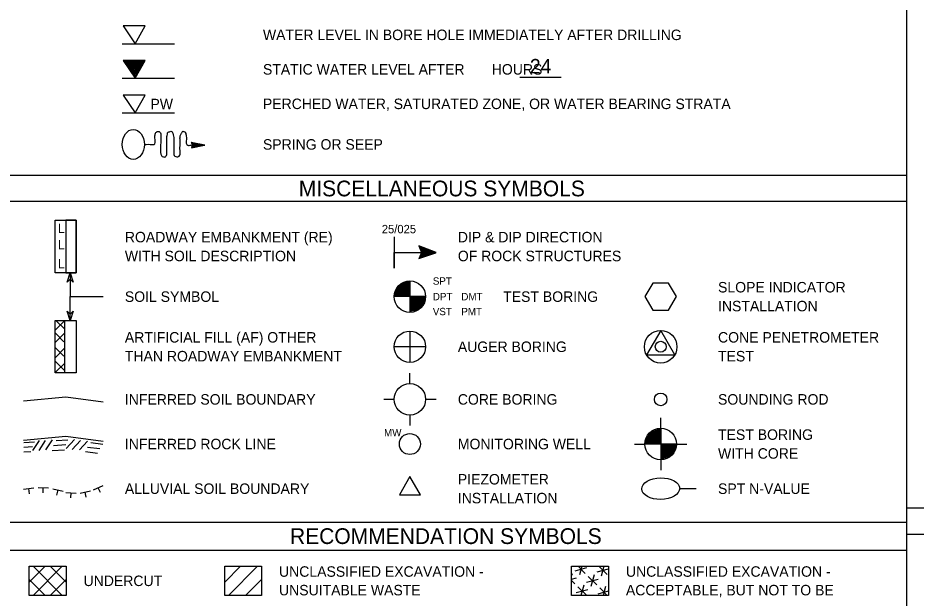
# Model space of a CAD drawing. Extents: x 278618 to 280654, y 171155 to 171855.
# Drawn here: x 280512.35 to 280549.54, y 171574.37 to 171598.38 of the extents above; entities that cross this region are included whole.
import ezdxf

# ---------------------------------------------------------------- set-up
doc = ezdxf.new("R2010")
doc.units = 0
doc.layers.add('Geotech Sheets and Borders Cell', color=7, linetype='Continuous')

msp = doc.modelspace()

# ---------------------------------------------------------------- linework, layer by layer
at = {"layer": 'Geotech Sheets and Borders Cell'}
for p, q in [((280549.148, 171621.702), (280549.148, 171541.488)), ((280516.664, 171597.314), (280518.833, 171597.314)), ((280516.664, 171595.886), (280518.833, 171595.886)), ((280533.134, 171595.924), (280534.838, 171595.924)), ((280516.664, 171594.459), (280518.833, 171594.459)), ((280520.093, 171593.12), (280519.52, 171593.228)), ((280519.52, 171593.228), (280519.581, 171593.124)), ((280519.581, 171593.124), (280519.529, 171593.011)), ((280519.529, 171593.011), (280520.079, 171593.115)), ((280519.568, 171593.102), (280519.819, 171593.15)), ((280519.568, 171593.102), (280519.819, 171593.15)), ((280519.568, 171593.098), (280519.819, 171593.146)), ((280519.568, 171593.094), (280519.819, 171593.141)), ((280519.568, 171593.089), (280519.819, 171593.137)), ((280519.568, 171593.085), (280519.819, 171593.133)), ((280519.568, 171593.085), (280519.819, 171593.133)), ((280519.572, 171593.081), (280519.824, 171593.128)), ((280519.572, 171593.076), (280519.824, 171593.124)), ((280519.572, 171593.072), (280519.824, 171593.12)), ((280519.572, 171593.068), (280519.824, 171593.115)), ((280519.572, 171593.063), (280519.824, 171593.111)), ((280519.572, 171593.059), (280519.824, 171593.107)), ((280519.572, 171593.059), (280519.824, 171593.107)), ((280519.576, 171593.141), (280519.832, 171593.098)), ((280519.576, 171593.141), (280519.832, 171593.098)), ((280519.576, 171593.137), (280519.832, 171593.094)), ((280519.576, 171593.055), (280519.828, 171593.102)), ((280519.576, 171593.05), (280519.828, 171593.098)), ((280519.576, 171593.046), (280519.828, 171593.094)), ((280519.576, 171593.042), (280519.828, 171593.089)), ((280519.576, 171593.042), (280519.828, 171593.089)), ((280519.576, 171593.037), (280519.828, 171593.085)), ((280519.581, 171593.172), (280519.837, 171593.128)), ((280519.581, 171593.167), (280519.837, 171593.124)), ((280519.581, 171593.163), (280519.837, 171593.12)), ((280519.581, 171593.159), (280519.837, 171593.115)), ((280519.581, 171593.154), (280519.837, 171593.111)), ((280519.581, 171593.15), (280519.837, 171593.107)), ((280519.581, 171593.033), (280519.832, 171593.081)), ((280519.585, 171593.193), (280519.841, 171593.15)), ((280519.585, 171593.185), (280519.841, 171593.141)), ((280519.585, 171593.18), (280519.841, 171593.137)), ((280519.585, 171593.176), (280519.841, 171593.133)), ((280519.589, 171593.198), (280519.845, 171593.154)), ((280519.594, 171593.206), (280520.062, 171593.12)), ((280549.148, 171591.865), (280474.148, 171591.865)), ((280549.148, 171590.781), (280474.148, 171590.781)), ((280514.329, 171590.004), (280514.329, 171587.835)), ((280528.578, 171587.496), (280528.578, 171586.195)), ((280529.229, 171586.846), (280527.928, 171586.846)), ((280513.9, 171585.47), (280514.273, 171585.843)), ((280514.273, 171585.509), (280513.921, 171585.861)), ((280514.281, 171585.83), (280514.281, 171583.679)), ((280513.891, 171584.941), (280514.281, 171585.332)), ((280514.255, 171584.98), (280513.9, 171585.336)), ((280528.578, 171585.423), (280528.578, 171584.121)), ((280514.255, 171584.386), (280513.908, 171584.733)), ((280529.229, 171584.772), (280527.928, 171584.772)), ((280513.9, 171584.329), (280514.281, 171584.711)), ((280513.904, 171583.713), (280514.286, 171584.095)), ((280514.277, 171583.792), (280513.908, 171584.16)), ((280528.578, 171583.248), (280528.578, 171583.682)), ((280527.494, 171582.597), (280527.928, 171582.597)), ((280529.229, 171582.597), (280529.663, 171582.597)), ((280528.578, 171581.947), (280528.578, 171581.513)), ((280538.965, 171581.396), (280538.965, 171581.83)), ((280538.965, 171581.396), (280538.965, 171580.095)), ((280512.599, 171580.811), (280513.037, 171580.842)), ((280512.599, 171580.62), (280512.946, 171580.642)), ((280512.963, 171580.473), (280513.237, 171580.889)), ((280513.224, 171580.477), (280513.493, 171580.894)), ((280513.51, 171580.508), (280513.779, 171580.924)), ((280513.822, 171580.686), (280514.33, 171580.72)), ((280513.926, 171580.889), (280514.421, 171580.92)), ((280514.351, 171580.564), (280514.69, 171580.928)), ((280514.599, 171580.521), (280514.941, 171580.889)), ((280514.898, 171580.499), (280515.228, 171580.863)), ((280515.371, 171580.803), (280515.865, 171580.746)), ((280537.88, 171580.746), (280538.314, 171580.746)), ((280539.615, 171580.746), (280538.314, 171580.746)), ((280539.615, 171580.746), (280540.049, 171580.746)), ((280512.599, 171580.417), (280512.885, 171580.434)), ((280513.77, 171580.482), (280514.273, 171580.512)), ((280515.145, 171580.434), (280515.644, 171580.369)), ((280515.228, 171580.62), (280515.74, 171580.564)), ((280538.965, 171580.095), (280538.965, 171579.661)), ((280512.581, 171578.876), (280513.011, 171578.937)), ((280512.828, 171578.69), (280512.798, 171578.907)), ((280513.18, 171578.941), (280513.614, 171578.928)), ((280513.392, 171578.72), (280513.397, 171578.933)), ((280513.8, 171578.898), (280514.221, 171578.789)), ((280513.956, 171578.633), (280514.013, 171578.846)), ((280514.924, 171578.711), (280515.349, 171578.802)), ((280515.475, 171578.85), (280515.874, 171579.024)), ((280515.761, 171578.737), (280515.674, 171578.937)), ((280539.752, 171578.909), (280540.438, 171578.909)), ((280514.329, 171578.737), (280514.763, 171578.716)), ((280514.538, 171578.512), (280514.546, 171578.724)), ((280515.18, 171578.547), (280515.136, 171578.759)), ((280549.148, 171578.101), (280588.802, 171578.101)), ((280474.148, 171577.514), (280549.148, 171577.514)), ((280549.148, 171577.016), (280588.802, 171577.016)), ((280474.148, 171576.353), (280549.148, 171576.353)), ((280512.854, 171575.686), (280512.817, 171575.649)), ((280513.474, 171575.686), (280512.817, 171575.029)), ((280514.181, 171575.686), (280512.977, 171574.482)), ((280512.977, 171575.686), (280514.181, 171574.482)), ((280513.684, 171575.686), (280514.341, 171575.029)), ((280520.91, 171575.029), (280521.567, 171575.686)), ((280521.071, 171574.482), (280522.274, 171575.686)), ((280535.423, 171575.504), (280535.906, 171575.633)), ((280535.547, 171575.686), (280535.841, 171575.392)), ((280535.696, 171575.686), (280535.6, 171575.327)), ((280536.33, 171575.456), (280536.801, 171575.583)), ((280536.407, 171575.686), (280536.748, 171575.344)), ((280536.616, 171575.686), (280536.507, 171575.28)), ((280512.817, 171575.139), (280513.474, 171574.482)), ((280514.341, 171575.139), (280513.684, 171574.482)), ((280521.778, 171574.482), (280522.434, 171575.139)), ((280535.299, 171575.38), (280535.277, 171575.298)), ((280535.277, 171575.15), (280535.476, 171575.203)), ((280535.277, 171575.096), (280535.411, 171574.962)), ((280535.9, 171575.026), (280536.383, 171575.156)), ((280535.965, 171575.268), (280536.318, 171574.914)), ((280536.206, 171575.333), (280536.077, 171574.85)), ((280535.47, 171574.596), (280535.953, 171574.726)), ((280535.535, 171574.838), (280535.888, 171574.484)), ((280535.776, 171574.903), (280535.664, 171574.482)), ((280536.442, 171574.791), (280536.75, 171574.482)), ((280536.684, 171574.855), (280536.584, 171574.482)), ((280536.377, 171574.549), (280536.801, 171574.663))]:
    msp.add_line(p, q, dxfattribs=at)
for points in [[(280517.198, 171597.314), (280517.622, 171598.048), (280516.711, 171598.048), (280517.198, 171597.314)], [(280517.198, 171595.886), (280517.622, 171596.619), (280516.711, 171596.619), (280517.198, 171595.886)], [(280516.755, 171596.593), (280517.592, 171596.593), (280517.197, 171595.925), (280516.755, 171596.593)], [(280516.802, 171596.567), (280517.553, 171596.567), (280517.197, 171595.964), (280516.811, 171596.545), (280517.527, 171596.545), (280517.197, 171596.003), (280516.846, 171596.524), (280517.488, 171596.524), (280517.197, 171596.051), (280516.893, 171596.498), (280517.444, 171596.498), (280517.193, 171596.098), (280516.933, 171596.472), (280517.401, 171596.467), (280517.188, 171596.142), (280516.976, 171596.446), (280517.366, 171596.446), (280517.188, 171596.181), (280517.019, 171596.424), (280517.327, 171596.424), (280517.188, 171596.229), (280517.063, 171596.406), (280517.293, 171596.406), (280517.193, 171596.268), (280517.11, 171596.385), (280517.249, 171596.385), (280517.188, 171596.289), (280517.149, 171596.363), (280517.219, 171596.367), (280517.188, 171596.333)], [(280517.198, 171594.459), (280517.622, 171595.191), (280516.711, 171595.191), (280517.198, 171594.459)], [(280519.529, 171593.224), (280519.589, 171593.12), (280519.589, 171593.211), (280519.533, 171593.224), (280519.585, 171593.137), (280519.585, 171593.206), (280519.542, 171593.215), (280519.581, 171593.15), (280519.581, 171593.202), (280519.55, 171593.206), (280519.576, 171593.172), (280519.576, 171593.163), (280519.576, 171593.193), (280519.559, 171593.198), (280519.576, 171593.198), (280519.568, 171593.185), (280519.594, 171593.115), (280519.585, 171593.115), (280519.581, 171593.111), (280519.537, 171593.015), (280519.581, 171593.024), (280519.594, 171593.115), (280519.585, 171593.107), (280519.546, 171593.02), (280519.576, 171593.028), (280519.585, 171593.102), (280519.555, 171593.024), (280519.572, 171593.033), (280519.576, 171593.076), (280519.563, 171593.028), (280519.589, 171593.028), (280520.071, 171593.12)], [(280519.845, 171593.15), (280520.045, 171593.12), (280519.837, 171593.081), (280519.845, 171593.146), (280520.019, 171593.12), (280519.841, 171593.089), (280519.85, 171593.137), (280519.993, 171593.115), (280519.971, 171593.124), (280519.845, 171593.141), (280519.845, 171593.094), (280519.98, 171593.115), (280519.85, 171593.133), (280519.845, 171593.102), (280519.958, 171593.115), (280519.85, 171593.128), (280519.854, 171593.107), (280519.936, 171593.12), (280519.85, 171593.124), (280519.85, 171593.107), (280519.906, 171593.124), (280519.854, 171593.115), (280519.85, 171593.098), (280519.91, 171593.107), (280519.854, 171593.154), (280519.936, 171593.137), (280519.845, 171593.154), (280519.589, 171593.124), (280519.615, 171593.115), (280519.624, 171593.12), (280519.624, 171593.124), (280519.646, 171593.124), (280519.646, 171593.128), (280519.602, 171593.189), (280519.685, 171593.172), (280519.68, 171593.185), (280519.594, 171593.202)], [(280519.594, 171593.128), (280519.633, 171593.12), (280519.589, 171593.111), (280519.693, 171593.133), (280519.594, 171593.141), (280519.68, 171593.124), (280519.659, 171593.141), (280519.589, 171593.193), (280519.785, 171593.154), (280519.841, 171593.146), (280519.837, 171593.076), (280519.828, 171593.111)], [(280527.927, 171589.32), (280527.927, 171588.019), (280527.927, 171588.67), (280529.663, 171588.67), (280528.956, 171588.943), (280529.064, 171588.67), (280528.96, 171588.444), (280528.947, 171588.418), (280529.654, 171588.665), (280529.081, 171588.657), (280528.973, 171588.435), (280529.589, 171588.648), (280529.212, 171588.648), (280529.086, 171588.644), (280528.995, 171588.457), (280529.528, 171588.639), (280529.099, 171588.639), (280529.025, 171588.479), (280529.489, 171588.639), (280529.06, 171588.622), (280529.112, 171588.613), (280529.038, 171588.488), (280529.116, 171588.639), (280529.437, 171588.622), (280529.064, 171588.501), (280529.133, 171588.618), (280529.394, 171588.618), (280529.09, 171588.527), (280529.138, 171588.609), (280529.324, 171588.609), (280529.12, 171588.544), (280529.142, 171588.605), (280529.255, 171588.605), (280529.146, 171588.566), (280529.159, 171588.592), (280529.212, 171588.587), (280529.172, 171588.579), (280529.086, 171588.54), (280529.112, 171588.596), (280529.064, 171588.505), (280529.012, 171588.479), (280529.081, 171588.622), (280529.034, 171588.791), (280528.977, 171588.917), (280529.615, 171588.678), (280529.073, 171588.687), (280529.572, 171588.696), (280529.003, 171588.9), (280529.081, 171588.678), (280529.502, 171588.7), (280529.09, 171588.7), (280529.029, 171588.878), (280529.06, 171588.856), (280529.09, 171588.713), (280529.077, 171588.856), (280529.511, 171588.704), (280529.103, 171588.713), (280529.086, 171588.83), (280529.45, 171588.722), (280529.112, 171588.726), (280529.398, 171588.726), (280529.099, 171588.817), (280529.346, 171588.726), (280529.09, 171588.8), (280529.116, 171588.743), (280529.29, 171588.722), (280529.155, 171588.752), (280529.099, 171588.748), (280529.107, 171588.774), (280529.294, 171588.739), (280529.116, 171588.783), (280529.081, 171588.852), (280529.268, 171588.778), (280529.029, 171588.874), (280529.09, 171588.804), (280529.047, 171588.848), (280529.064, 171588.817), (280529.073, 171588.796)], [(280514.511, 171587.835), (280514.511, 171586.846), (280515.874, 171586.846)], [(280527.936, 171586.867), (280528.574, 171586.875), (280527.936, 171586.88), (280527.971, 171586.884), (280528.574, 171586.893), (280527.936, 171586.901), (280528.57, 171586.914), (280527.945, 171586.919), (280528.57, 171586.932), (280527.941, 171586.945), (280528.574, 171586.953), (280527.954, 171586.966), (280528.574, 171586.979), (280527.958, 171586.992), (280528.57, 171587.005), (280527.958, 171587.018), (280528.574, 171587.023), (280527.975, 171587.044), (280528.574, 171587.044), (280527.98, 171587.066), (280528.574, 171587.066), (280527.988, 171587.092), (280528.578, 171587.088), (280528.006, 171587.118), (280528.574, 171587.114), (280528.019, 171587.149), (280528.578, 171587.136), (280528.045, 171587.179), (280528.578, 171587.166), (280528.058, 171587.205), (280528.574, 171587.192), (280528.084, 171587.235), (280528.574, 171587.227), (280528.11, 171587.266), (280528.574, 171587.253), (280528.136, 171587.296), (280528.583, 171587.279), (280528.175, 171587.331), (280528.574, 171587.313), (280528.218, 171587.361), (280528.574, 171587.348), (280528.275, 171587.391), (280528.574, 171587.383), (280528.348, 171587.426), (280528.57, 171587.417), (280528.439, 171587.444), (280528.574, 171587.452), (280528.509, 171587.465)], [(280538.64, 171586.282), (280539.29, 171586.282), (280539.616, 171586.846), (280539.29, 171587.41), (280538.64, 171587.41), (280538.314, 171586.846), (280538.64, 171586.282)], [(280514.511, 171585.856), (280514.511, 171586.85)], [(280529.217, 171586.829), (280528.579, 171586.82), (280529.217, 171586.816), (280529.182, 171586.811), (280528.579, 171586.803), (280529.217, 171586.794), (280528.583, 171586.781), (280529.208, 171586.776), (280528.583, 171586.763), (280529.212, 171586.75), (280528.579, 171586.742), (280529.199, 171586.729), (280528.579, 171586.716), (280529.195, 171586.703), (280528.583, 171586.69), (280529.195, 171586.677), (280528.579, 171586.672), (280529.178, 171586.651), (280528.579, 171586.651), (280529.173, 171586.629), (280528.579, 171586.629), (280529.165, 171586.603), (280528.575, 171586.607), (280529.147, 171586.577), (280528.579, 171586.581), (280529.134, 171586.547), (280528.575, 171586.56), (280529.108, 171586.516), (280528.575, 171586.529), (280529.095, 171586.49), (280528.579, 171586.503), (280529.069, 171586.46), (280528.579, 171586.468), (280529.043, 171586.429), (280528.579, 171586.442), (280529.017, 171586.399), (280528.57, 171586.416), (280528.978, 171586.364), (280528.579, 171586.382), (280528.935, 171586.334), (280528.579, 171586.347), (280528.878, 171586.304), (280528.579, 171586.312), (280528.805, 171586.269), (280528.583, 171586.278), (280528.713, 171586.252), (280528.579, 171586.243), (280528.644, 171586.23)], [(280512.581, 171582.53), (280514.338, 171582.697), (280515.874, 171582.489)], [(280512.581, 171580.909), (280514.334, 171581.076), (280515.874, 171580.867)], [(280538.322, 171580.767), (280538.96, 171580.775), (280538.322, 171580.78), (280538.357, 171580.784), (280538.96, 171580.793), (280538.322, 171580.801), (280538.956, 171580.814), (280538.331, 171580.819), (280538.956, 171580.832), (280538.327, 171580.845), (280538.96, 171580.853), (280538.34, 171580.866), (280538.96, 171580.879), (280538.344, 171580.892), (280538.956, 171580.905), (280538.344, 171580.918), (280538.96, 171580.923), (280538.361, 171580.944), (280538.96, 171580.944), (280538.366, 171580.966), (280538.96, 171580.966), (280538.374, 171580.992), (280538.964, 171580.988), (280538.392, 171581.018), (280538.96, 171581.014), (280538.405, 171581.049), (280538.964, 171581.036), (280538.431, 171581.079), (280538.964, 171581.066), (280538.444, 171581.105), (280538.96, 171581.092), (280538.47, 171581.135), (280538.96, 171581.127), (280538.496, 171581.166), (280538.96, 171581.153), (280538.522, 171581.196), (280538.969, 171581.179), (280538.561, 171581.231), (280538.96, 171581.213), (280538.604, 171581.261), (280538.96, 171581.248), (280538.661, 171581.291), (280538.96, 171581.283), (280538.734, 171581.326), (280538.956, 171581.317), (280538.825, 171581.344), (280538.96, 171581.352), (280538.895, 171581.365)], [(280539.603, 171580.729), (280538.965, 171580.72), (280539.603, 171580.716), (280539.568, 171580.711), (280538.965, 171580.703), (280539.603, 171580.694), (280538.969, 171580.681), (280539.594, 171580.676), (280538.969, 171580.663), (280539.598, 171580.65), (280538.965, 171580.642), (280539.585, 171580.629), (280538.965, 171580.616), (280539.581, 171580.603), (280538.969, 171580.59), (280539.581, 171580.577), (280538.965, 171580.572), (280539.564, 171580.551), (280538.965, 171580.551), (280539.559, 171580.529), (280538.965, 171580.529), (280539.551, 171580.503), (280538.961, 171580.507), (280539.533, 171580.477), (280538.965, 171580.481), (280539.52, 171580.447), (280538.961, 171580.46), (280539.494, 171580.416), (280538.961, 171580.429), (280539.481, 171580.39), (280538.965, 171580.403), (280539.455, 171580.36), (280538.965, 171580.368), (280539.429, 171580.329), (280538.965, 171580.342), (280539.403, 171580.299), (280538.956, 171580.316), (280539.364, 171580.264), (280538.965, 171580.282), (280539.321, 171580.234), (280538.965, 171580.247), (280539.264, 171580.204), (280538.965, 171580.212), (280539.191, 171580.169), (280538.969, 171580.178), (280539.099, 171580.152), (280538.965, 171580.143), (280539.03, 171580.13)], [(280528.145, 171578.648), (280529.012, 171578.648), (280528.579, 171579.398), (280528.145, 171578.648)]]:
    msp.add_lwpolyline(points, dxfattribs=at)
for points in [[(280513.895, 171590.004), (280514.763, 171590.004), (280514.763, 171587.835), (280513.895, 171587.835)], [(280514.329, 171587.835), (280514.763, 171587.835), (280514.763, 171590.004), (280514.329, 171590.004)], [(280514.381, 171587.445), (280514.511, 171587.835), (280514.641, 171587.445), (280514.511, 171587.575)], [(280514.641, 171586.246), (280514.511, 171585.856), (280514.381, 171586.246), (280514.511, 171586.116)], [(280513.895, 171585.856), (280514.763, 171585.856), (280514.763, 171583.687), (280513.895, 171583.687)], [(280538.965, 171585.447), (280538.38, 171584.435), (280539.549, 171584.435)], [(280512.817, 171575.686), (280514.341, 171575.686), (280514.341, 171574.482), (280512.817, 171574.482)], [(280520.91, 171575.686), (280522.434, 171575.686), (280522.434, 171574.482), (280520.91, 171574.482)], [(280535.277, 171575.686), (280536.801, 171575.686), (280536.801, 171574.482), (280535.277, 171574.482)]]:
    msp.add_lwpolyline(points, close=True, dxfattribs=at)
for centre, radius in [((280528.578, 171586.846), 0.651), ((280528.578, 171584.772), 0.651), ((280528.578, 171582.597), 0.651), ((280538.965, 171582.593), 0.26), ((280538.965, 171580.746), 0.651), ((280528.578, 171580.746), 0.434)]:
    msp.add_circle(centre, radius, dxfattribs=at)
for centre, major_axis, ratio in [((280517.123, 171593.146), (0, -0.618), 0.743839), ((280538.965, 171584.772), (0, 0.675), 0.999997), ((280538.965, 171584.772), (0, 0.225), 0.999997), ((280538.965, 171578.898), (0.787, 0.011), 0.568627)]:
    msp.add_ellipse(centre, major_axis=major_axis, ratio=ratio, dxfattribs=at)
msp.add_spline([(280517.585, 171593.146), (280517.915, 171593.141), (280517.984, 171593.141), (280518.028, 171593.35), (280518.028, 171593.545), (280518.049, 171593.605), (280518.08, 171593.658), (280518.201, 171593.679), (280518.266, 171593.532), (280518.253, 171593.12), (280518.253, 171592.872), (280518.266, 171592.747), (280518.327, 171592.647), (280518.418, 171592.625), (280518.453, 171592.634), (280518.513, 171592.768), (280518.513, 171592.911), (280518.513, 171593.336), (280518.513, 171593.471), (280518.535, 171593.575), (280518.566, 171593.658), (280518.618, 171593.666), (280518.678, 171593.688), (280518.73, 171593.666), (280518.761, 171593.605), (280518.804, 171593.367), (280518.804, 171592.946), (280518.804, 171592.829), (280518.821, 171592.694), (280518.887, 171592.647), (280518.969, 171592.634), (280519.03, 171592.664), (280519.06, 171592.747), (280519.06, 171592.872), (280519.06, 171593.358), (280519.06, 171593.449), (280519.09, 171593.553), (280519.121, 171593.605), (280519.155, 171593.658), (280519.186, 171593.688), (280519.225, 171593.679), (280519.277, 171593.636), (280519.307, 171593.566), (280519.32, 171593.484), (280519.32, 171593.297), (280519.32, 171593.193), (280519.381, 171593.111), (280519.516, 171593.12), (280519.763, 171593.12), (280520.093, 171593.12)], degree=3, dxfattribs=at)

# ---------------------------------------------------------------- texts
for s, height, p in [('WATER LEVEL IN BORE HOLE IMMEDIATELY AFTER DRILLING', 0.43381, (280522.494, 171597.464)), ('24', 0.6, (280533.547, 171596.082)), ('STATIC WATER LEVEL AFTER       HOURS', 0.43381, (280522.494, 171596.036)), ('PW', 0.4338, (280517.835, 171594.602)), ('PERCHED WATER, SATURATED ZONE, OR WATER BEARING STRATA', 0.43381, (280522.494, 171594.608)), ('SPRING OR SEEP', 0.43381, (280522.494, 171592.929)), ('MISCELLANEOUS SYMBOLS', 0.6507, (280523.978, 171590.997)), ('L', 0.39, (280514.003, 171589.474)), ('25/025', 0.347, (280527.416, 171589.468)), ('L', 0.39, (280514.003, 171588.806)), ('ROADWAY EMBANKMENT (RE)', 0.43381, (280516.776, 171589.093)), ('DIP & DIP DIRECTION', 0.43381, (280530.565, 171589.093)), ('WITH SOIL DESCRIPTION', 0.43381, (280516.776, 171588.312)), ('OF ROCK STRUCTURES', 0.43381, (280530.565, 171588.312)), ('L', 0.39, (280514.003, 171588.016)), ('SPT', 0.3037, (280529.529, 171587.34)), ('SLOPE INDICATOR', 0.43381, (280541.34, 171587.019)), ('SOIL SYMBOL', 0.43381, (280516.776, 171586.629)), ('DPT', 0.3037, (280529.529, 171586.694)), ('DMT', 0.3037, (280530.709, 171586.694)), ('TEST BORING', 0.43381, (280532.443, 171586.629)), ('INSTALLATION', 0.43381, (280541.34, 171586.238)), ('VST', 0.3037, (280529.529, 171586.078)), ('PMT', 0.3037, (280530.709, 171586.078)), ('ARTIFICIAL FILL (AF) OTHER', 0.43381, (280516.776, 171584.945)), ('CONE PENETROMETER', 0.43381, (280541.34, 171584.945)), ('AUGER BORING', 0.43381, (280530.565, 171584.555)), ('THAN ROADWAY EMBANKMENT', 0.43381, (280516.776, 171584.165)), ('TEST', 0.4338, (280541.34, 171584.165)), ('INFERRED SOIL BOUNDARY', 0.43381, (280516.776, 171582.376)), ('CORE BORING', 0.43381, (280530.565, 171582.376)), ('SOUNDING ROD', 0.43381, (280541.34, 171582.376)), ('TEST BORING', 0.43381, (280541.34, 171580.919)), ('INFERRED ROCK LINE', 0.43381, (280516.776, 171580.529)), ('MONITORING WELL', 0.43381, (280530.565, 171580.529)), ('WITH CORE ', 0.4338, (280541.34, 171580.138)), ('PIEZOMETER', 0.4338, (280530.565, 171579.071)), ('ALLUVIAL SOIL BOUNDARY', 0.43381, (280516.776, 171578.681)), ('SPT N-VALUE', 0.43381, (280541.34, 171578.681)), ('INSTALLATION', 0.43381, (280530.565, 171578.291)), ('RECOMMENDATION SYMBOLS', 0.6507, (280523.614, 171576.608)), ('UNCLASSIFIED EXCAVATION -', 0.43381, (280523.16, 171575.252)), ('UNCLASSIFIED EXCAVATION -', 0.43381, (280537.526, 171575.252)), ('UNDERCUT', 0.4338, (280515.066, 171574.867)), ('UNSUITABLE WASTE', 0.43381, (280523.16, 171574.482)), ('ACCEPTABLE, BUT NOT TO BE', 0.43381, (280537.526, 171574.482))]:
    msp.add_text(s, height=height, dxfattribs=at).set_placement(p)
msp.add_text('MW', height=0.3037, rotation=360, dxfattribs=at).set_placement((280527.509, 171581.065))

doc.saveas('drawing.dxf')
